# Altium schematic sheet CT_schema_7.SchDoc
size 251 x 159 mm
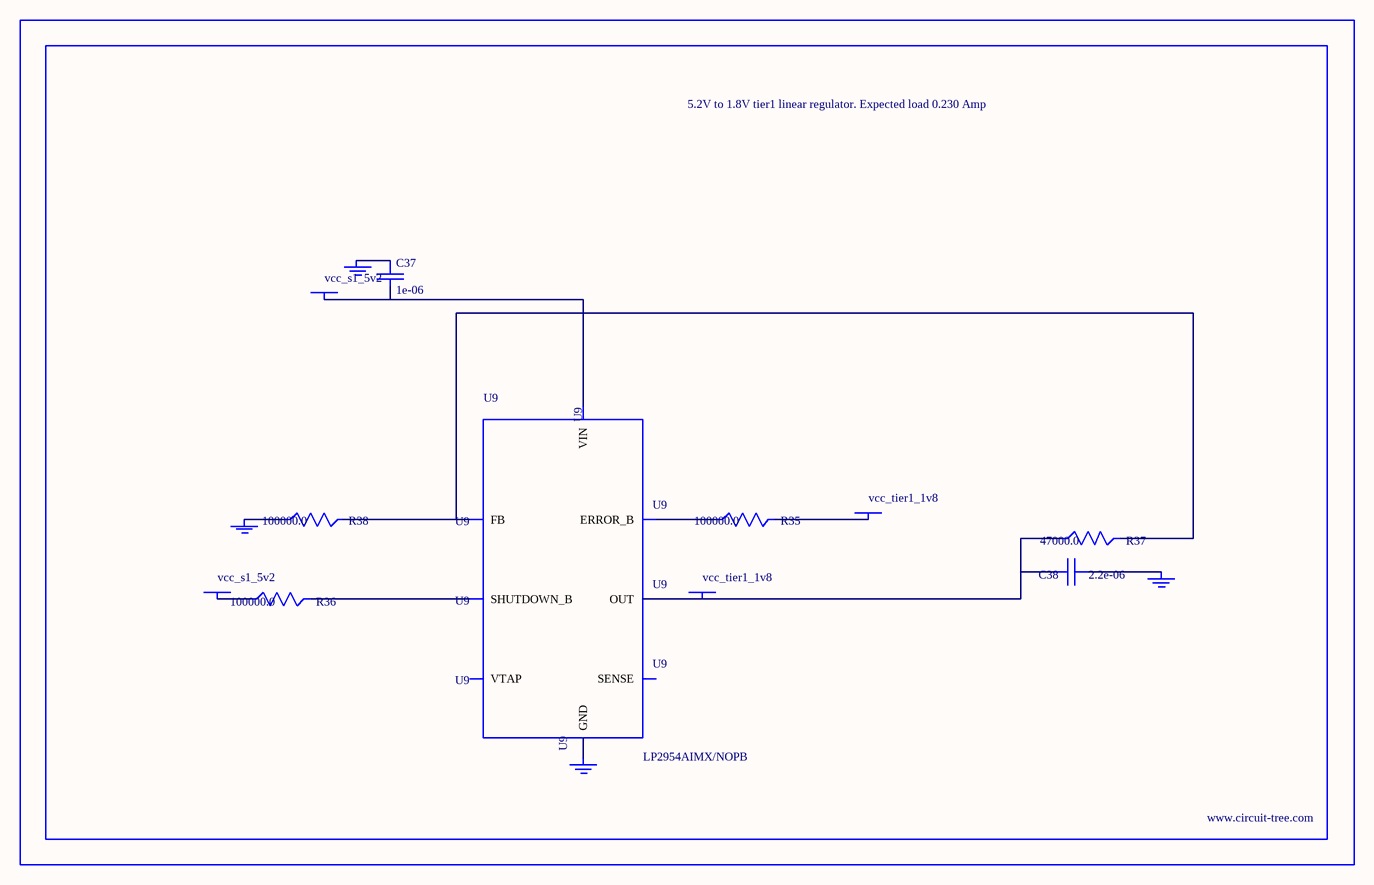
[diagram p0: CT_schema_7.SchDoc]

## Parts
BORDER6  (no value)
C37  1e-06  [EXV-9B]
C38  2.2e-06  [EXV-9B]
GND_INSTANCE_6_0  (no value)
GND_INSTANCE_6_1  (no value)
GND_INSTANCE_6_2  (no value)
GND_INSTANCE_6_3  (no value)
POWER_INSTANCE_6_0  vcc_s1_5v2
POWER_INSTANCE_6_1  vcc_tier1_1v8
POWER_INSTANCE_6_2  vcc_s1_5v2
POWER_INSTANCE_6_3  vcc_tier1_1v8
R35  100000.0  [R0603]
R36  100000.0  [R0603]
R37  47000.0  [R0603]
R38  100000.0  [R0603]
U9  LP2954AIMX/NOPB  [LP2954]

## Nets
NetC37_1: C37.1 GND_INSTANCE_6_2.0(GND)
NetC37_2: C37.2 POWER_INSTANCE_6_2.0(PWR) U9.8(VIN)
NetC38_1: C38.1 GND_INSTANCE_6_0.0(GND)
NetC38_2: C38.2 POWER_INSTANCE_6_3.0(PWR) R37.1 U9.1(OUT)
NetGND_INSTANCE_6_1_0: GND_INSTANCE_6_1.0(GND) R38.1
NetGND_INSTANCE_6_3_0: GND_INSTANCE_6_3.0(GND) U9.4(GND)
NetPOWER_INSTANCE_6_0_0: POWER_INSTANCE_6_0.0(PWR) R36.1
NetPOWER_INSTANCE_6_1_0: POWER_INSTANCE_6_1.0(PWR) R35.2
NetR35_1: R35.1 U9.5(ERROR_B)
NetR36_2: R36.2 U9.3(SHUTDOWN_B)
NetR37_2: R37.2 R38.2 U9.7(FB)

Not connected (* = marked no-connect by the designer): U9 2(SENSE) 6(VTAP)

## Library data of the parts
BORDER6 = BORDER_PAGE6
C37 = EDK105M050A9BAA
C38 = EDK225M050A9BAA
GND_INSTANCE_6_0-GND_INSTANCE_6_3 = GND
POWER_INSTANCE_6_0-POWER_INSTANCE_6_3 = PWR
R35 R36 R38 = RC0603JR-07100KL
R37 = RC0603JR-0747KL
